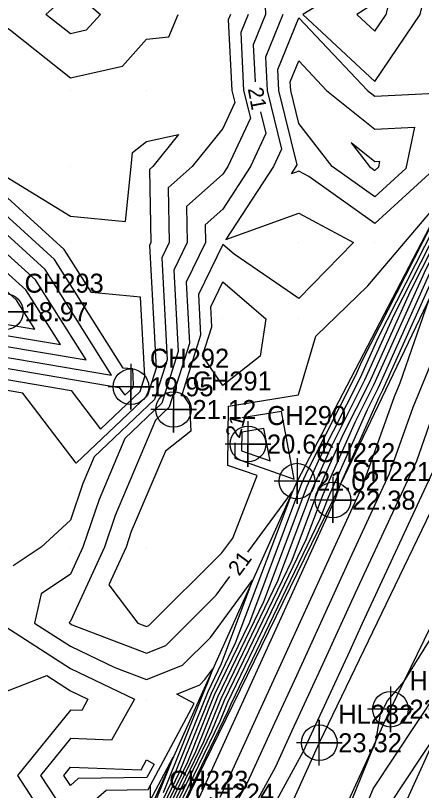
# Model space of a CAD drawing. Extents: x 2531902 to 2533249, y 715219 to 716099.
# Drawn here: x 2532862.8 to 2532916.1, y 715718 to 715819.8 of the extents above; entities that cross this region are included whole.
import ezdxf

# ---------------------------------------------------------------- set-up
doc = ezdxf.new("R2010")
doc.units = 0
for name, color, linetype in [('DTM Contours Major', 7, 'Continuous'), ('DTM Contours Major Text', 7, 'Continuous'), ('DTM Contours Minor', 7, 'Continuous'), ('Exist DTM Breakline', 7, 'Continuous'), ('Exist DTM Breakline Cogo Elevation', 7, 'Continuous'), ('Exist DTM Breakline Cogo Number', 7, 'Continuous'), ('Exist DTM Breakline Cogo Point CELL', 7, 'Continuous'), ('Exist DTM Crownline', 7, 'Continuous'), ('Exist DTM Crownline Cogo Elevation', 7, 'Continuous'), ('Exist DTM Crownline Cogo Number', 7, 'Continuous'), ('Exist DTM Crownline Cogo Point CELL', 7, 'Continuous'), ('Exist DTM QL2 LIDAR Elevation Point', 7, 'Continuous'), ('Exist DTM Regular Point CELL', 7, 'Continuous'), ('Exist DTM Regular Point Cogo Elevation', 7, 'Continuous'), ('Exist DTM Regular Point Cogo Number', 7, 'Continuous'), ('Exist Roads Soil', 7, 'Continuous'), ('Exist Roads Soil Cogo Elevation', 7, 'Continuous'), ('Exist Roads Soil Cogo Number', 7, 'Continuous'), ('Exist Roads Soil Cogo Point CELL', 7, 'Continuous')]:
    doc.layers.add(name, color=color, linetype=linetype)

msp = doc.modelspace()

# ---------------------------------------------------------------- linework, layer by layer
at = {"layer": 'DTM Contours Major'}
for points in [[(2532895.35, 715872.64), (2532896.87, 715873.13), (2532900, 715875.04), (2532907.12, 715880), (2532908.45, 715881.55), (2532910, 715881.53), (2532915.09, 715880), (2532917.15, 715877.15), (2532914.44, 715870), (2532913.6, 715866.4), (2532912.3, 715857.26), (2532910.43, 715850.04), (2532901.6, 715840.97), (2532901.31, 715840), (2532901.08, 715838.92), (2532900.88, 715830), (2532901.02, 715828.98), (2532900, 715828.35), (2532895.45, 715824.55), (2532895.61, 715820), (2532894, 715816), (2532894.25, 715811.12)], [(2532894.98, 715807.21), (2532895.68, 715804.32), (2532893.66, 715800), (2532890, 715794.39), (2532887.68, 715792.32), (2532887.73, 715790), (2532885.21, 715784.79), (2532885.63, 715776.76), (2532882.98, 715768.37), (2532881.18, 715766.67), (2532875.87, 715754.13), (2532874.47, 715750), (2532870, 715740.24), (2532869.86, 715740.14), (2532869.83, 715740), (2532870, 715739.89), (2532870.22, 715739.78), (2532880, 715736.07), (2532882.51, 715737.08), (2532889.16, 715743.68), (2532890.94, 715746.11)], [(2532924.51, 715801.84), (2532922.71, 715798.38), (2532916.68, 715786.53), (2532909.83, 715771.26), (2532907.4, 715766.44), (2532903.16, 715756.87), (2532900.93, 715750.96), (2532890.63, 715729.59), (2532889.62, 715727.08), (2532883.37, 715714.16), (2532882.09, 715711.33)], [(2532827.84, 715792.78), (2532830.78, 715791.25), (2532838.31, 715784.29), (2532846.58, 715780.28), (2532853.68, 715773.51), (2532860.49, 715773.66), (2532876.38, 715770.97), (2532877.15, 715769.95), (2532878.18, 715770.93), (2532878.3, 715771.33), (2532878.2, 715773.4), (2532876.91, 715773.51), (2532867.91, 715787.78), (2532860.41, 715794.59), (2532853.47, 715794.23), (2532849.97, 715796.34)], [(2532926.4, 715790.98), (2532921.2, 715776.01), (2532917.46, 715766.94), (2532915.45, 715761.3), (2532907.4, 715743.93), (2532903.18, 715734.67), (2532899.09, 715725.84), (2532896.93, 715721.12), (2532887.61, 715704.05), (2532886.84, 715702.63), (2532884.88, 715700.29)], [(2532899.4, 715758.94), (2532897.72, 715767.79), (2532892.51, 715766.96)], [(2532891.6, 715763.7), (2532891.59, 715761.69), (2532899.4, 715758.94)], [(2532898.85, 715671.67), (2532899.31, 715677.66), (2532903.18, 715693.14), (2532903.31, 715695.06), (2532903.3, 715695.22), (2532902.83, 715701.16), (2532909.79, 715718.24), (2532918.3, 715731.09), (2532918.77, 715732.55), (2532920.73, 715735.31), (2532923.9, 715740.41), (2532930.87, 715758.95), (2532930.93, 715759.06), (2532933.35, 715763.75)], [(2532893.31, 715749.34), (2532899.16, 715757.29), (2532891.65, 715737.36), (2532888.47, 715730.76), (2532884.29, 715720.39), (2532881.68, 715715), (2532875.66, 715701.65), (2532869.22, 715687.73), (2532867.84, 715684.68), (2532864.86, 715678.23), (2532862.92, 715674.85)]]:
    msp.add_lwpolyline(points, dxfattribs=at)
at = {"layer": 'DTM Contours Minor'}
for points in [[(2532978.6, 715897.02), (2532971.54, 715883.73), (2532964.38, 715870.65), (2532963.04, 715868.12), (2532962.03, 715866.27), (2532956.1, 715855.79), (2532947.49, 715840), (2532946.01, 715837.37), (2532942.98, 715831.81), (2532929.46, 715806.65), (2532928.8, 715805.39), (2532926.84, 715801.79), (2532925.94, 715798.41), (2532924.88, 715795.79), (2532917.24, 715773.78), (2532915, 715768.35), (2532911.89, 715759.64), (2532906.46, 715747.9), (2532899.69, 715733.07), (2532896.81, 715726.84), (2532893.28, 715719.11), (2532886.56, 715706.8)], [(2532979.49, 715896.63), (2532969.07, 715877.05), (2532965.34, 715870.24), (2532963.42, 715866.61), (2532962.93, 715865.71), (2532960.03, 715860.58), (2532948.47, 715839.39), (2532948.02, 715838.58), (2532944.02, 715831.24), (2532940.5, 715824.7), (2532936.19, 715810.14), (2532935.67, 715806.57), (2532934.81, 715803.32), (2532928.11, 715786.71), (2532925.17, 715778.24), (2532919.92, 715765.54), (2532919, 715762.97), (2532908.34, 715739.96), (2532906.66, 715736.27), (2532901.37, 715724.85), (2532900.58, 715723.13), (2532888.66, 715701.29)], [(2532975.24, 715893.74), (2532962.94, 715871.27), (2532962.47, 715870.38), (2532960.68, 715867.11), (2532950.2, 715848.59), (2532946.02, 715840.92), (2532942.99, 715835.54), (2532941.43, 715832.67), (2532934.44, 715819.68), (2532927.43, 715806.14), (2532924.67, 715801.08), (2532923.15, 715798.13), (2532918.78, 715789.56), (2532910.43, 715770.93), (2532908.97, 715768.04), (2532903.85, 715756.51), (2532902.79, 715753.68), (2532891.06, 715729.36), (2532890.68, 715728.42), (2532883.71, 715713.99)], [(2532974, 715890.4), (2532963.42, 715871.07), (2532962.66, 715869.63), (2532961.13, 715866.83), (2532952.17, 715850.99), (2532946.51, 715840.61), (2532943.99, 715836.15), (2532941.95, 715832.38), (2532932.78, 715815.34), (2532927.89, 715805.89), (2532924.52, 715799.72), (2532923.58, 715797.89), (2532920.87, 715792.58), (2532911.02, 715770.61), (2532910.53, 715769.63), (2532905.46, 715758.2), (2532904.79, 715756.31), (2532904.57, 715755.84), (2532892.72, 715729.86), (2532892.24, 715728.82), (2532885.98, 715715.09)], [(2532972.77, 715887.07), (2532963.9, 715870.86), (2532962.85, 715868.87), (2532961.58, 715866.55), (2532954.13, 715853.39), (2532947, 715840.3), (2532945, 715836.76), (2532942.46, 715832.1), (2532931.12, 715810.99), (2532928.35, 715805.64), (2532924.37, 715798.35), (2532924.01, 715797.65), (2532922.97, 715795.61), (2532917.04, 715782.38), (2532913.28, 715771.54), (2532912.54, 715769.75), (2532908.34, 715757.97), (2532905.51, 715751.87), (2532896.21, 715731.46), (2532894.52, 715727.83), (2532889.63, 715717.1)], [(2532916.81, 715870), (2532915.52, 715864.48), (2532914.61, 715858.08), (2532912.28, 715849.07), (2532908.39, 715845.07), (2532906.85, 715840), (2532905.65, 715834.35), (2532905.56, 715830), (2532906.4, 715823.6), (2532900.55, 715820), (2532910, 715811.18), (2532915.94, 715820), (2532916.76, 715823.24)], [(2532916.48, 715863.52), (2532915.77, 715858.5), (2532913.21, 715848.58), (2532911.78, 715847.11), (2532909.62, 715840), (2532907.94, 715832.06), (2532907.89, 715830), (2532909.09, 715820.91), (2532907.62, 715820), (2532910, 715817.78), (2532911.5, 715820), (2532913.21, 715826.79), (2532920, 715826.92)], [(2532868.47, 715821.53), (2532870, 715823.39), (2532873.94, 715820), (2532872.08, 715817.92), (2532870, 715817.45), (2532866.78, 715820), (2532868.47, 715821.53)], [(2532833.18, 715821.51), (2532837.83, 715818.33), (2532840, 715813.53), (2532843.33, 715816.67), (2532850, 715819.92), (2532850.17, 715819.83), (2532860, 715819.36), (2532862.1, 715817.9), (2532870, 715811.65), (2532876.83, 715813.17), (2532880, 715816.74), (2532882.94, 715817.06), (2532884.15, 715820)], [(2532891.04, 715820), (2532890.74, 715819.26), (2532891.21, 715810), (2532891.59, 715808.41), (2532890, 715805), (2532885.98, 715800), (2532882.82, 715797.18), (2532882.96, 715790), (2532882, 715788), (2532882.7, 715774.59), (2532881.06, 715769.4), (2532873.11, 715761.86), (2532871.63, 715758.37), (2532870, 715753.53), (2532866.14, 715750), (2532862.47, 715747.53)], [(2532893.33, 715820), (2532892.37, 715817.63), (2532892.75, 715810), (2532893.64, 715806.36), (2532890.66, 715800), (2532890, 715798.99), (2532885.25, 715794.75), (2532885.34, 715790), (2532883.6, 715786.4), (2532884.17, 715775.68), (2532882.02, 715768.89), (2532877.15, 715764.26), (2532873.75, 715756.25), (2532871.64, 715750), (2532870, 715746.42), (2532866.16, 715743.84), (2532865.29, 715740), (2532870, 715736.96), (2532875.85, 715734.15), (2532880, 715732.58), (2532884.74, 715734.49), (2532888.41, 715738.13), (2532893.94, 715745.65), (2532889.79, 715734.64), (2532888.03, 715730.99), (2532883.22, 715719.06), (2532881.34, 715715.17)], [(2532897.89, 715820), (2532895.63, 715814.37), (2532895.85, 715810), (2532897.73, 715802.27), (2532896.67, 715800), (2532890.4, 715790.4), (2532900, 715793.86), (2532907.19, 715790), (2532900, 715782.68), (2532891.53, 715788.47), (2532890, 715789.77), (2532886.82, 715783.18), (2532887.1, 715777.85), (2532884.66, 715770.14), (2532885.64, 715768.7), (2532885.82, 715765.23), (2532882.47, 715762.59), (2532877.98, 715752.02), (2532877.3, 715750), (2532875.02, 715745.02), (2532878.86, 715740), (2532880, 715739.57), (2532880.28, 715739.68), (2532889.9, 715749.22), (2532891.33, 715751.18), (2532894.53, 715759.38), (2532890.69, 715760.73), (2532890.76, 715768.53), (2532899.95, 715770), (2532899.98, 715770.02), (2532900, 715770.17), (2532902.24, 715777.72), (2532909.06, 715784.33), (2532919.7, 715796.83), (2532908.29, 715774.43), (2532907.45, 715772.56), (2532901.15, 715760.06), (2532900.38, 715758.33), (2532893.51, 715740.08), (2532888.9, 715730.53), (2532885.36, 715721.73), (2532882.02, 715714.83)], [(2532899.77, 715800.23), (2532897.4, 715810), (2532897.26, 715812.74), (2532900, 715819.55), (2532909.04, 715810), (2532910, 715809.23), (2532919.72, 715809.72), (2532917.65, 715799.54), (2532910, 715792.53), (2532901.32, 715798.68), (2532900, 715799.39), (2532899.04, 715799.04), (2532899.67, 715800), (2532899.77, 715800.23)], [(2532829.15, 715791.09), (2532830.3, 715790.49), (2532839.05, 715782.4), (2532843.68, 715780.16), (2532852.17, 715772.07), (2532860.3, 715772.25), (2532870.07, 715770.59), (2532873.94, 715765.49), (2532879.14, 715770.42), (2532879.77, 715772.41), (2532879.22, 715782.84), (2532872.75, 715783.43), (2532869.17, 715789.12), (2532860.21, 715797.25), (2532851.92, 715796.81), (2532847.61, 715799.41), (2532838.98, 715807.73), (2532836.79, 715809.08), (2532833.95, 715815.36), (2532830.27, 715817.88)], [(2532826.53, 715794.46), (2532831.25, 715792.01), (2532837.56, 715786.18), (2532849.47, 715780.41), (2532855.19, 715774.95), (2532860.68, 715775.07), (2532875.41, 715772.57), (2532866.66, 715786.45), (2532860.62, 715791.94), (2532855.02, 715791.64), (2532843.74, 715798.45), (2532837.51, 715804.46), (2532832.17, 715807.75), (2532830.07, 715812.39), (2532827.35, 715814.25)], [(2532898.95, 715810), (2532898.89, 715811.11), (2532900, 715813.87), (2532903.66, 715810), (2532910, 715804.93), (2532915.19, 715805.19), (2532914.08, 715799.75), (2532910, 715796.02), (2532904.37, 715800), (2532900, 715805.66), (2532898.95, 715810)], [(2532825.22, 715796.15), (2532831.72, 715792.78), (2532836.82, 715788.06), (2532852.36, 715780.53), (2532856.7, 715776.39), (2532860.86, 715776.48), (2532872.04, 715774.59), (2532865.4, 715785.12), (2532860.82, 715789.28), (2532856.57, 715789.06), (2532841.81, 715797.97), (2532836.78, 715802.82), (2532829.86, 715807.09), (2532828.13, 715810.91), (2532825.89, 715812.44)], [(2532823.91, 715797.84), (2532832.2, 715793.54), (2532836.08, 715789.95), (2532855.25, 715780.66), (2532858.22, 715777.83), (2532861.05, 715777.9), (2532868.68, 715776.6), (2532864.15, 715783.78), (2532861.02, 715786.62), (2532858.13, 715786.47), (2532839.87, 715797.49), (2532836.04, 715801.19), (2532827.55, 715806.42), (2532826.19, 715809.42), (2532824.44, 715810.62)], [(2532822.59, 715799.52), (2532832.67, 715794.3), (2532835.33, 715791.84), (2532858.14, 715780.78), (2532859.73, 715779.27), (2532861.24, 715779.31), (2532865.31, 715778.62), (2532862.89, 715782.45), (2532861.22, 715783.97), (2532859.68, 715783.89), (2532837.94, 715797.02), (2532835.31, 715799.55), (2532825.24, 715805.76), (2532824.25, 715807.93), (2532822.98, 715808.81)], [(2532860.94, 715799.06), (2532870, 715793.5), (2532877.21, 715792.79), (2532877.96, 715800), (2532878.17, 715801.83), (2532880, 715803.27), (2532884.21, 715804.21), (2532880.83, 715800), (2532880.39, 715799.61), (2532880.58, 715790), (2532880.39, 715789.61), (2532881.24, 715773.5), (2532880.1, 715769.91), (2532870.73, 715761.02), (2532863.75, 715770.22), (2532860.11, 715770.84)], [(2532910.52, 715799.97), (2532910.66, 715800.66), (2532910, 715800.62), (2532906.88, 715803.12), (2532909.29, 715800), (2532910, 715799.5), (2532910.52, 715799.97)], [(2532921.41, 715799.11), (2532910.39, 715777.45), (2532908.05, 715772.24), (2532902.71, 715761.66), (2532901.07, 715757.97), (2532895.36, 715742.8), (2532889.33, 715730.29), (2532886.42, 715723.07), (2532882.36, 715714.66)], [(2532921.85, 715798.87), (2532912.48, 715780.48), (2532908.64, 715771.91), (2532904.28, 715763.25), (2532901.77, 715757.6), (2532897.22, 715745.52), (2532889.76, 715730.06), (2532887.49, 715724.41), (2532882.69, 715714.49)], [(2532922.28, 715798.62), (2532914.58, 715783.5), (2532909.24, 715771.58), (2532905.84, 715764.85), (2532902.46, 715757.24), (2532899.07, 715748.24), (2532890.2, 715729.82), (2532888.55, 715725.74), (2532883.03, 715714.33)], [(2532888.57, 715778.94), (2532888.43, 715781.57), (2532890, 715784.83), (2532895.68, 715780), (2532894.93, 715775.07), (2532890, 715771.22), (2532887.36, 715775.13), (2532888.57, 715778.94)], [(2532896.24, 715761.32), (2532895.43, 715765.58), (2532892.51, 715765.11), (2532892.48, 715762.64), (2532896.24, 715761.32)], [(2532899.42, 715698.21), (2532909.74, 715723.53), (2532909.89, 715723.76), (2532910.11, 715724.45), (2532910.72, 715728.06), (2532911.66, 715729.77), (2532913.8, 715732.27), (2532924.72, 715749.82)], [(2532860.75, 715740), (2532870, 715734.03), (2532878.4, 715730), (2532875.37, 715724.63), (2532870, 715724.82), (2532866.08, 715720), (2532870, 715713.96), (2532874.69, 715718.03), (2532880.2, 715718.12), (2532886.26, 715729.42), (2532883.97, 715730.68), (2532886.98, 715731.89), (2532887.67, 715732.58), (2532888.72, 715734.01), (2532887.94, 715731.92), (2532887.6, 715731.23), (2532882.16, 715717.72)], [(2532860, 715730.43), (2532866.88, 715733.12), (2532870, 715731.11), (2532872.3, 715730), (2532871.48, 715728.52), (2532870, 715728.58), (2532863.03, 715720), (2532868.61, 715711.39)], [(2532909.84, 715712.94), (2532918.23, 715725.63)], [(2532880.37, 715716.53), (2532883.51, 715722.37), (2532881.09, 715716.38)], [(2532869.14, 715720), (2532870, 715721.06), (2532879.27, 715720.73), (2532880, 715722.02), (2532880.98, 715721.48), (2532880.03, 715719.7), (2532871.03, 715719.57), (2532870, 715718.67), (2532869.14, 715720)]]:
    msp.add_lwpolyline(points, dxfattribs=at)
at = {"layer": 'Exist DTM Breakline'}
for points in [[(2533023.85, 715972.82), (2532999.03, 715934.39), (2532976.75, 715897.83), (2532959.92, 715867.59), (2532939.77, 715833.59), (2532921.01, 715799.34), (2532899.77, 715758.66), (2532880.47, 715715.6), (2532864.43, 715683.53), (2532849.72, 715661.42)], [(2533029.09, 715973.62), (2533002.14, 715931.72), (2532981.11, 715895.92), (2532963.78, 715865.17), (2532944.31, 715831.08), (2532924.28, 715797.5), (2532904.49, 715756.17), (2532883.85, 715713.92), (2532865.56, 715669.75), (2532864.57, 715660.11), (2532866.15, 715657.26), (2532867.93, 715656.56)]]:
    msp.add_lwpolyline(points, dxfattribs=at)
at = {"layer": 'Exist DTM Breakline Cogo Point CELL'}
for points in [[(2532899.77, 715761.66), (2532899.77, 715755.66), (2532899.77, 715758.66), (2532902.77, 715758.66), (2532896.77, 715758.66)], [(2532904.49, 715759.17), (2532904.49, 715753.17), (2532904.49, 715756.17), (2532907.49, 715756.17), (2532901.49, 715756.17)], [(2532880.47, 715718.6), (2532880.47, 715712.6), (2532880.47, 715715.6), (2532883.47, 715715.6), (2532877.47, 715715.6)]]:
    msp.add_lwpolyline(points, dxfattribs=at)
for centre in [(2532899.77, 715758.66), (2532904.49, 715756.17)]:
    msp.add_circle(centre, 2.34, dxfattribs=at)
at = {"layer": 'Exist DTM Crownline'}
msp.add_lwpolyline([(2532876.57, 715652.01), (2532884.04, 715667.73), (2532897.27, 715696.35), (2532912.05, 715728.69), (2532925.33, 715755.88), (2532939.89, 715784.74), (2532958.95, 715822.25), (2532974.27, 715850.52), (2532997.48, 715891.38), (2533017.87, 715925.25), (2533038.84, 715957.69)], dxfattribs=at)
at = {"layer": 'Exist DTM Crownline Cogo Point CELL'}
msp.add_lwpolyline([(2532912.05, 715731.69), (2532912.05, 715725.69), (2532912.05, 715728.69), (2532915.05, 715728.69), (2532909.05, 715728.69)], dxfattribs=at)
msp.add_circle((2532912.05, 715728.69), 2.34, dxfattribs=at)
at = {"layer": 'Exist DTM QL2 LIDAR Elevation Point'}
for p, q in [((2532870, 715810), (2532870, 715810)), ((2532880, 715810), (2532880, 715810)), ((2532890, 715810), (2532890, 715810)), ((2532900, 715810), (2532900, 715810)), ((2532910, 715810), (2532910, 715810)), ((2532870, 715800), (2532870, 715800)), ((2532880, 715800), (2532880, 715800)), ((2532890, 715800), (2532890, 715800)), ((2532900, 715800), (2532900, 715800)), ((2532910, 715800), (2532910, 715800)), ((2532870, 715790), (2532870, 715790)), ((2532880, 715790), (2532880, 715790)), ((2532890, 715790), (2532890, 715790)), ((2532900, 715790), (2532900, 715790)), ((2532910, 715790), (2532910, 715790)), ((2532870, 715780), (2532870, 715780)), ((2532880, 715780), (2532880, 715780)), ((2532890, 715780), (2532890, 715780)), ((2532900, 715780), (2532900, 715780)), ((2532870, 715770), (2532870, 715770)), ((2532890, 715770), (2532890, 715770)), ((2532900, 715770), (2532900, 715770)), ((2532870, 715760), (2532870, 715760)), ((2532880, 715760), (2532880, 715760)), ((2532890, 715760), (2532890, 715760)), ((2532870, 715750), (2532870, 715750)), ((2532880, 715750), (2532880, 715750)), ((2532890, 715750), (2532890, 715750)), ((2532870, 715740), (2532870, 715740)), ((2532880, 715740), (2532880, 715740)), ((2532870, 715730), (2532870, 715730)), ((2532880, 715730), (2532880, 715730)), ((2532870, 715720), (2532870, 715720)), ((2532880, 715720), (2532880, 715720))]:
    msp.add_line(p, q, dxfattribs=at)
at = {"layer": 'Exist DTM Regular Point CELL'}
for points in [[(2532861.46, 715783.92), (2532861.46, 715777.92), (2532861.46, 715780.92), (2532864.46, 715780.92), (2532858.46, 715780.92)], [(2532877.94, 715774.06), (2532877.94, 715768.06), (2532877.94, 715771.06), (2532880.94, 715771.06), (2532874.94, 715771.06)], [(2532883.54, 715771.07), (2532883.54, 715765.07), (2532883.54, 715768.07), (2532886.54, 715768.07), (2532880.54, 715768.07)], [(2532893.32, 715766.53), (2532893.32, 715760.53), (2532893.32, 715763.53), (2532896.32, 715763.53), (2532890.32, 715763.53)]]:
    msp.add_lwpolyline(points, dxfattribs=at)
for centre in [(2532861.46, 715780.92), (2532877.94, 715771.06), (2532883.54, 715768.07), (2532893.32, 715763.53)]:
    msp.add_circle(centre, 2.34, dxfattribs=at)
at = {"layer": 'Exist Roads Soil'}
for points in [[(2533033, 715963.55), (2533014.44, 715935.48), (2532992.67, 715901.09), (2532976.47, 715871.31), (2532962.05, 715845.13), (2532943.27, 715807.99), (2532921.98, 715764.36), (2532902.69, 715724.28), (2532889.07, 715694.2), (2532879.25, 715673.17), (2532870.65, 715655.41), (2532876.57, 715652.01), (2532882.44, 715649.38)], [(2532882.44, 715649.38), (2532884.45, 715653.58), (2532893.83, 715673.24), (2532904.08, 715695.07), (2532909.89, 715707.28), (2532923.66, 715737.55), (2532935.37, 715761.59), (2532947.64, 715787.12), (2532960.72, 715812.47), (2532979.3, 715846.3), (2532995.34, 715875.46), (2533008.57, 715897.69), (2533027.7, 715928.62), (2533038.6, 715945.65), (2533044.8, 715955.28)]]:
    msp.add_lwpolyline(points, dxfattribs=at)
at = {"layer": 'Exist Roads Soil Cogo Point CELL'}
msp.add_lwpolyline([(2532902.69, 715721.28), (2532902.69, 715727.28), (2532902.69, 715724.28), (2532905.69, 715724.28), (2532899.69, 715724.28)], dxfattribs=at)
msp.add_circle((2532902.69, 715724.28), 2.34, dxfattribs=at)

# ---------------------------------------------------------------- texts
at = {"layer": 'DTM Contours Major Text'}
for rotation, p in [(280.6321, (2532893.29, 715810.23)), (74.5045, (2532892.24, 715764.19)), (53.7025, (2532892.17, 715746.09))]:
    msp.add_text('21', height=2, rotation=rotation, dxfattribs=at).set_placement(p)
at = {"layer": 'Exist DTM Breakline Cogo Elevation'}
for s, p in [('21.02', (2532902.27, 715757.41)), ('22.38', (2532906.99, 715754.92))]:
    msp.add_text(s, height=2.5, dxfattribs=at).set_placement(p)
at = {"layer": 'Exist DTM Breakline Cogo Number'}
for s, p in [('CH222', (2532902.27, 715761.16)), ('CH221', (2532906.99, 715758.67)), ('CH223', (2532882.97, 715718.1)), ('CH224', (2532886.35, 715716.42))]:
    msp.add_text(s, height=2.5, dxfattribs=at).set_placement(p)
at = {"layer": 'Exist DTM Crownline Cogo Elevation'}
msp.add_text('23.18', height=2.5, dxfattribs=at).set_placement((2532914.55, 715727.44))
at = {"layer": 'Exist DTM Crownline Cogo Number'}
msp.add_text('HL265', height=2.5, dxfattribs=at).set_placement((2532914.55, 715731.19))
at = {"layer": 'Exist DTM Regular Point Cogo Elevation'}
for s, p in [('18.97', (2532863.96, 715779.67)), ('19.95', (2532880.44, 715769.81)), ('21.12', (2532886.04, 715766.82)), ('20.61', (2532895.82, 715762.28))]:
    msp.add_text(s, height=2.5, dxfattribs=at).set_placement(p)
at = {"layer": 'Exist DTM Regular Point Cogo Number'}
for s, p in [('CH293', (2532863.96, 715783.42)), ('CH292', (2532880.44, 715773.56)), ('CH291', (2532886.04, 715770.57)), ('CH290', (2532895.82, 715766.03))]:
    msp.add_text(s, height=2.5, dxfattribs=at).set_placement(p)
at = {"layer": 'Exist Roads Soil Cogo Elevation'}
msp.add_text('23.32', height=2.5, dxfattribs=at).set_placement((2532905.19, 715723.03))
at = {"layer": 'Exist Roads Soil Cogo Number'}
msp.add_text('HL282', height=2.5, dxfattribs=at).set_placement((2532905.19, 715726.78))

doc.saveas('drawing.dxf')
